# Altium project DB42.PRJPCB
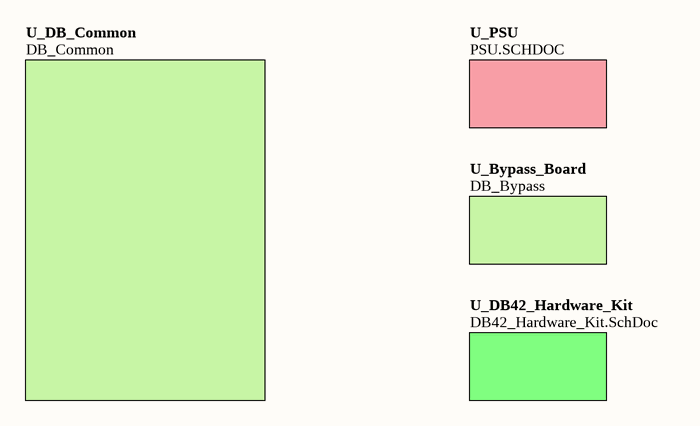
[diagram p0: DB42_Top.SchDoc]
ProjectAddress1: L3, 12A Rodborough Road; ProjectAddress2: Frenchs Forest; ProjectAddress3: NSW 2086; ProjectAddress4: Australia; ProjectAssyNum: D-820-0025; ProjectOrganization: Altium Limited; ProjectRevision: 01; ProjectTitle: DB42 - Daughter Board Spartan3; ProjectTotalSheets: 23
9 sheets, 129 parts. Net scope: hierarchical (ports join the sheet entries above them; power ports are global).
Board files: DB42.PcbDoc, DB42_Panel.PcbDoc
Sheets:
  DB42_Top.SchDoc
    U_PSU = PSU.SCHDOC
    U_DB42_Hardware_Kit = DB42_Hardware_Kit.SchDoc
  DEVICES.SchDoc
    U_FPGA = FPGA.SCHDOC
      U_FPGA_Power = FPGA_NonIO.SchDoc
      U_Bypass_3V3 = Bypass_FPGA_3V3.SchDoc
      U_Bypass_2V5 = Bypass_FPGA_2V5.SchDoc
      U_Bypass_1V2 = Bypass_FPGA_1V2.SchDoc

## Sheet DB42_Top.SchDoc: DB42 Top Level
size A4; Organization: Altium Limited.; Address1: Level 3, 12a Rodborough Rd; Address2: Frenchs Forest 2086; Address3: NSW; Address4: AUSTRALIA; DocumentNumber: 1; SheetNumber: 2; SheetTotal: 23

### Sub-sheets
U_Bypass_Board = DB_Bypass (file not in this document): no entries
U_DB42_Hardware_Kit = DB42_Hardware_Kit.SchDoc: no entries
U_DB_Common = DB_Common (file not in this document): no entries
U_PSU = PSU.SCHDOC: no entries

## Sheet PSU.SCHDOC: Power Supply Top Level
size A4; Organization: Altium Limited.; Address1: Level 3, 12a Rodborough Rd; Address2: Frenchs Forest 2086; Address3: NSW; Address4: AUSTRALIA; DocumentNumber: 10; SheetNumber: 10; SheetTotal: 23
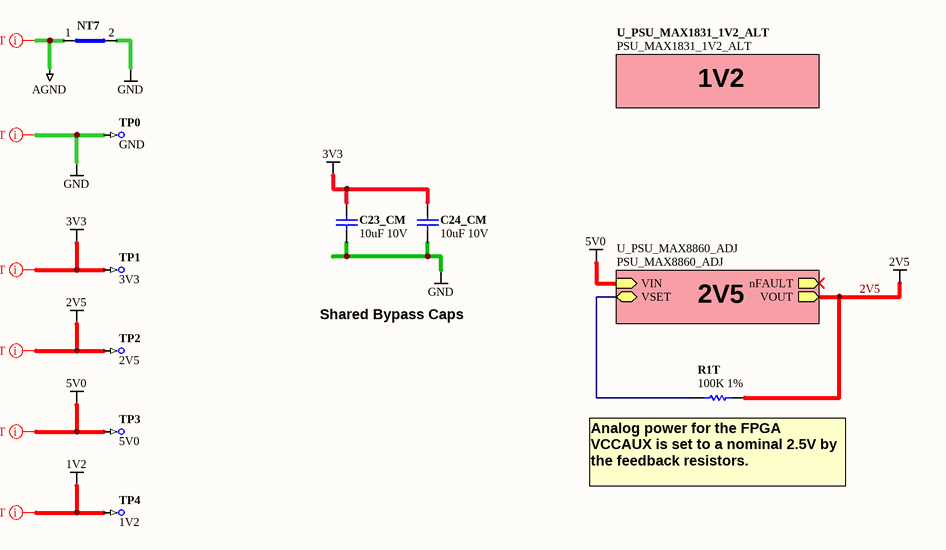
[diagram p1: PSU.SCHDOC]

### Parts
C23_CM  10uF 10V  [CAPC2012-STAR]
C24_CM  10uF 10V  [CAPC2012-STAR]
NT7  Net Tie SMT2  [NETTIE-SMT2-8X8]  (value not drawn)  (net tie, no BOM)
R1T  100K 1%  [RESC1005-STAR]
TP0  GND  [TestPin]  (no BOM)
TP1  3V3  [TestPin]  (no BOM)
TP2  2V5  [TestPin]  (no BOM)
TP3  5V0  [TestPin]  (no BOM)
TP4  1V2  [TestPin]  (no BOM)

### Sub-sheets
U_PSU_MAX1831_1V2_ALT = PSU_MAX1831_1V2_ALT (file not in this document): no entries
U_PSU_MAX8860_ADJ = PSU_MAX8860_ADJ (file not in this document): nFAULT (out), VIN (in), VOUT (out), VSET (bidir)

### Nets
1V2: TP4.1
2V5: R1T.2 TP2.1 ; sheet U_PSU_MAX8860_ADJ/VOUT
3V3: C23_CM.1 C24_CM.1 TP1.1
5V0: TP3.1 ; sheet U_PSU_MAX8860_ADJ/VIN
AGND: NT7.1(Net1)
GND: C23_CM.2 C24_CM.2 NT7.2(Net2) TP0.1
NetR1T_1: R1T.1 ; sheet U_PSU_MAX8860_ADJ/VSET

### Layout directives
net class PWRNET: 1V2, 2V5, 3V3, 5V0, AGND, GND

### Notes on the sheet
- 1V2
- Shared Bypass Caps
- 2V5
- (near R1T) Analog power for the FPGA VCCAUX is set to a nominal 2.5V by the feedback resistors.

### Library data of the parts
C23_CM C24_CM = D-101-0087: Capacitor, Ceramic, 10uF 10% 10V 0805 (2012) X5R; Polarity: Non-Polarized
NT7 = D-002-0002: Net-Tie, Surface Mount, 2 x 0.4mm x 0.2mm SMT Pads - For 0.2mm Track
R1T = D-100-0132: Resistor, 100K 1% 0402 (1005); Power Rating: 63 mW
TP0-TP4 = D-006-0000: Test Point, PCB Mount with Silkscreen Box

## Sheet DB42_Hardware_Kit.SchDoc: DB42 Hardware Kit
size A4; Organization: Altium Limited.; Address1: Level 3, 12a Rodborough Rd; Address2: Frenchs Forest 2086; Address3: NSW; Address4: AUSTRALIA; DocumentNumber: 9; SheetNumber: 9; SheetTotal: 23
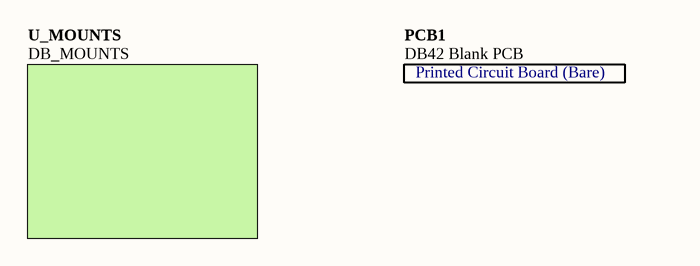
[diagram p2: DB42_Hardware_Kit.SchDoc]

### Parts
PCB1  DB42 Blank PCB  [DB42 Blank PCB]

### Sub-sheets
U_MOUNTS = DB_MOUNTS (file not in this document): no entries

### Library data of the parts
PCB1 = D-810-0025: DB42 Blank PCB - Daughter Board; ProjectPath: DB42.PrjPCB

## Sheet DEVICES.SchDoc: FPGA, LEDs and SRAM Memory
size A4; Organization: Altium Limited.; Address1: Level 3, 12a Rodborough Rd; Address2: Frenchs Forest 2086; Address3: NSW; Address4: AUSTRALIA; DocumentNumber: 2; SheetNumber: 3; SheetTotal: 23
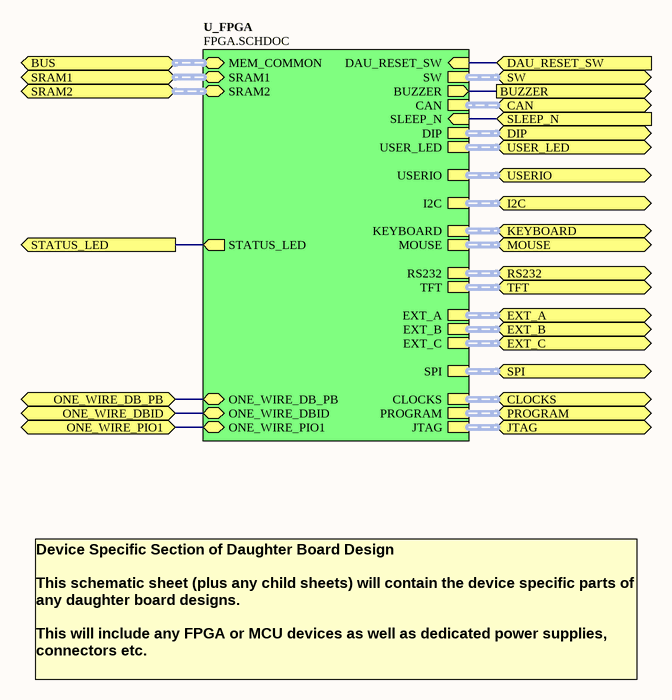
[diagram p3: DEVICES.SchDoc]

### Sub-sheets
U_FPGA = FPGA.SCHDOC: SRAM1 (harness SRAM-256Kx16), SRAM2 (harness SRAM-256Kx16), MEM_COMMON (harness HOSTMEMORY), DAU_RESET_SW (in), BUZZER (out), ONE_WIRE_DBID (bidir), ONE_WIRE_DB_PB (bidir), ONE_WIRE_PIO1 (bidir), JTAG (harness HardSoft_JTAG), SW (harness SW5), DIP (harness SW8), USERIO (harness IO36), EXT_A (harness PBIO), EXT_B (harness PBIO), EXT_C (harness PBIO), USER_LED (harness LED8), SPI (harness DAU_SPI), I2C (harness I2C), CAN (harness CAN_INT), RS232 (harness RS232_INT), KEYBOARD (harness PS2), MOUSE (harness PS2), TFT (harness DAU_TFT), PROGRAM (harness DAU_CTRL), CLOCKS (harness DAU_CLK), STATUS_LED (out), SLEEP_N (in)

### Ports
BUS (harness HOSTMEMORY), BUZZER (out), CAN, CLOCKS, DAU_RESET_SW (in), DIP, EXT_A, EXT_B, EXT_C, I2C, JTAG, KEYBOARD, MOUSE, ONE_WIRE_DB_PB (bidir), ONE_WIRE_DBID (bidir), ONE_WIRE_PIO1 (bidir), PROGRAM, RS232, SLEEP_N (in), SPI, SRAM1, SRAM2 (harness SRAM-256Kx16), STATUS_LED (out), SW, TFT, USER_LED, USERIO

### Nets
BUZZER: port BUZZER, sheet U_FPGA/BUZZER
DAU_RESET_SW: port DAU_RESET_SW, sheet U_FPGA/DAU_RESET_SW
ONE_WIRE_DB_PB: port ONE_WIRE_DB_PB, sheet U_FPGA/ONE_WIRE_DB_PB
ONE_WIRE_DBID: port ONE_WIRE_DBID, sheet U_FPGA/ONE_WIRE_DBID
ONE_WIRE_PIO1: port ONE_WIRE_PIO1, sheet U_FPGA/ONE_WIRE_PIO1
SLEEP_N: port SLEEP_N, sheet U_FPGA/SLEEP_N
STATUS_LED: port STATUS_LED, sheet U_FPGA/STATUS_LED

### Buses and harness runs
harness port BUS = sheet U_FPGA/MEM_COMMON
harness port CAN = sheet U_FPGA/CAN
harness port CLOCKS = sheet U_FPGA/CLOCKS
harness port DIP = sheet U_FPGA/DIP
harness port EXT_A = sheet U_FPGA/EXT_A
harness port EXT_B = sheet U_FPGA/EXT_B
harness port EXT_C = sheet U_FPGA/EXT_C
harness port I2C = sheet U_FPGA/I2C
harness port JTAG = sheet U_FPGA/JTAG
harness port KEYBOARD = sheet U_FPGA/KEYBOARD
harness port MOUSE = sheet U_FPGA/MOUSE
harness port PROGRAM = sheet U_FPGA/PROGRAM
harness port RS232 = sheet U_FPGA/RS232
harness port SPI = sheet U_FPGA/SPI
harness port SRAM1 = sheet U_FPGA/SRAM1
harness port SRAM2 = sheet U_FPGA/SRAM2
harness port SW = sheet U_FPGA/SW
harness port TFT = sheet U_FPGA/TFT
harness port USER_LED = sheet U_FPGA/USER_LED
harness port USERIO = sheet U_FPGA/USERIO

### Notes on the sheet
- Device Specific Section of Daughter Board Design
  This schematic sheet (plus any child sheets) will contain the device specific parts of any daughter board designs.
  This will include any FPGA or MCU devices as well as dedicated power supplies, connectors etc.

## Sheet FPGA.SCHDOC: FPGA Connections
size A2; Organization: Altium Limited.; Address1: Level 3, 12a Rodborough Rd; Address2: Frenchs Forest 2086; Address3: NSW; Address4: AUSTRALIA; DocumentNumber: 3; SheetNumber: 4; SheetTotal: 23; PageSetup: Record=PageOptions|CenterHorizontal=True|CenterVertical=True|PrintScale=0.71|XCorrection=1.00|YCorrection=1.00|PrintKind=0|BorderSize=5000000|LeftOffset=0|BottomOffset=0|Orientation=2|PaperLength=4199|PaperWidth=2969|Scale=100|PaperSource=7|PrintQuality=600|MediaType=1|DitherType=10|PaperKind=A3 (297 x 420 mm)|PrintScaleMode=1
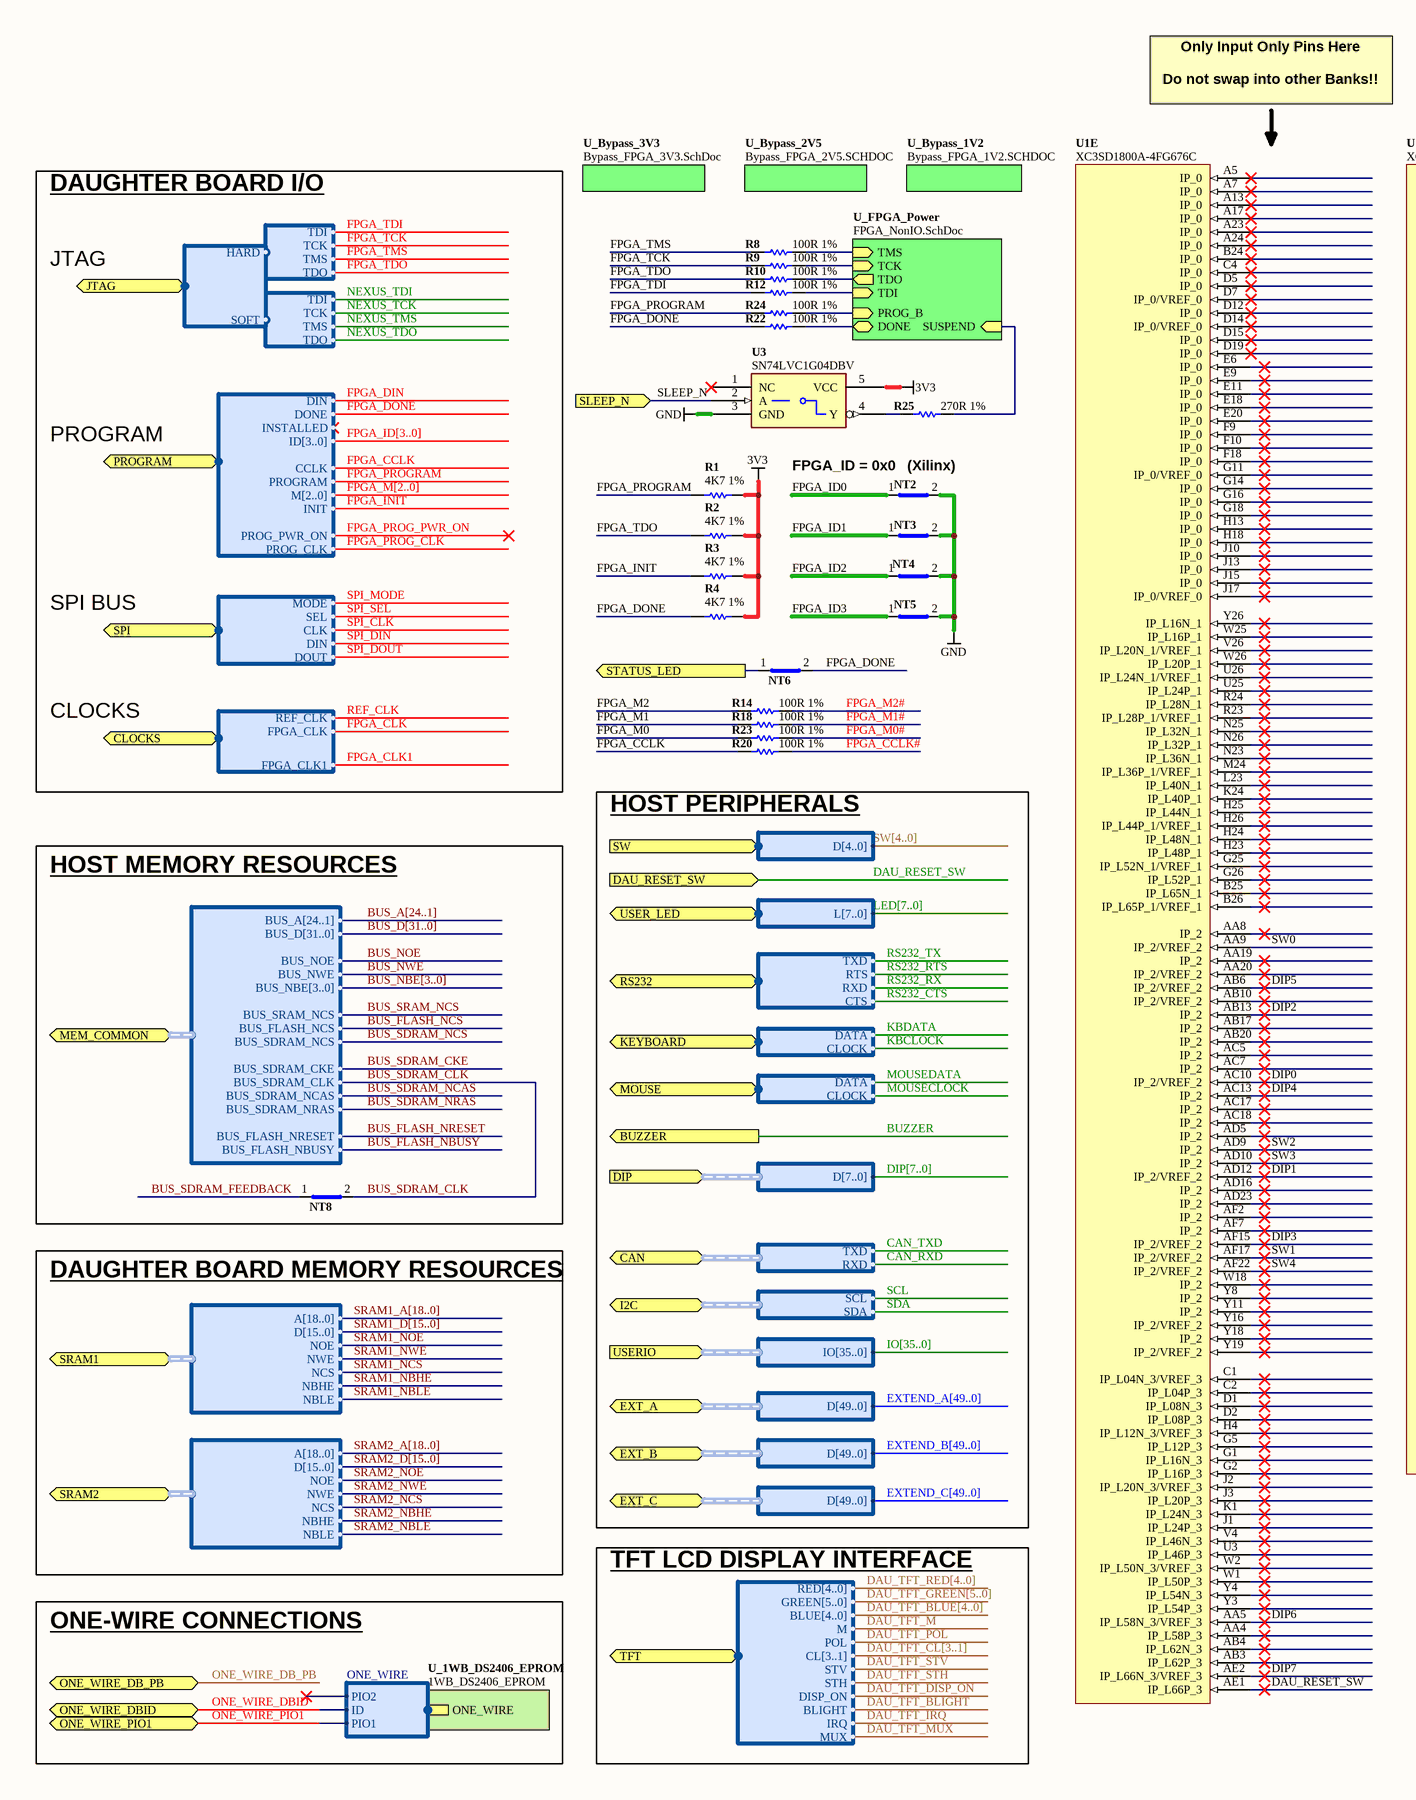
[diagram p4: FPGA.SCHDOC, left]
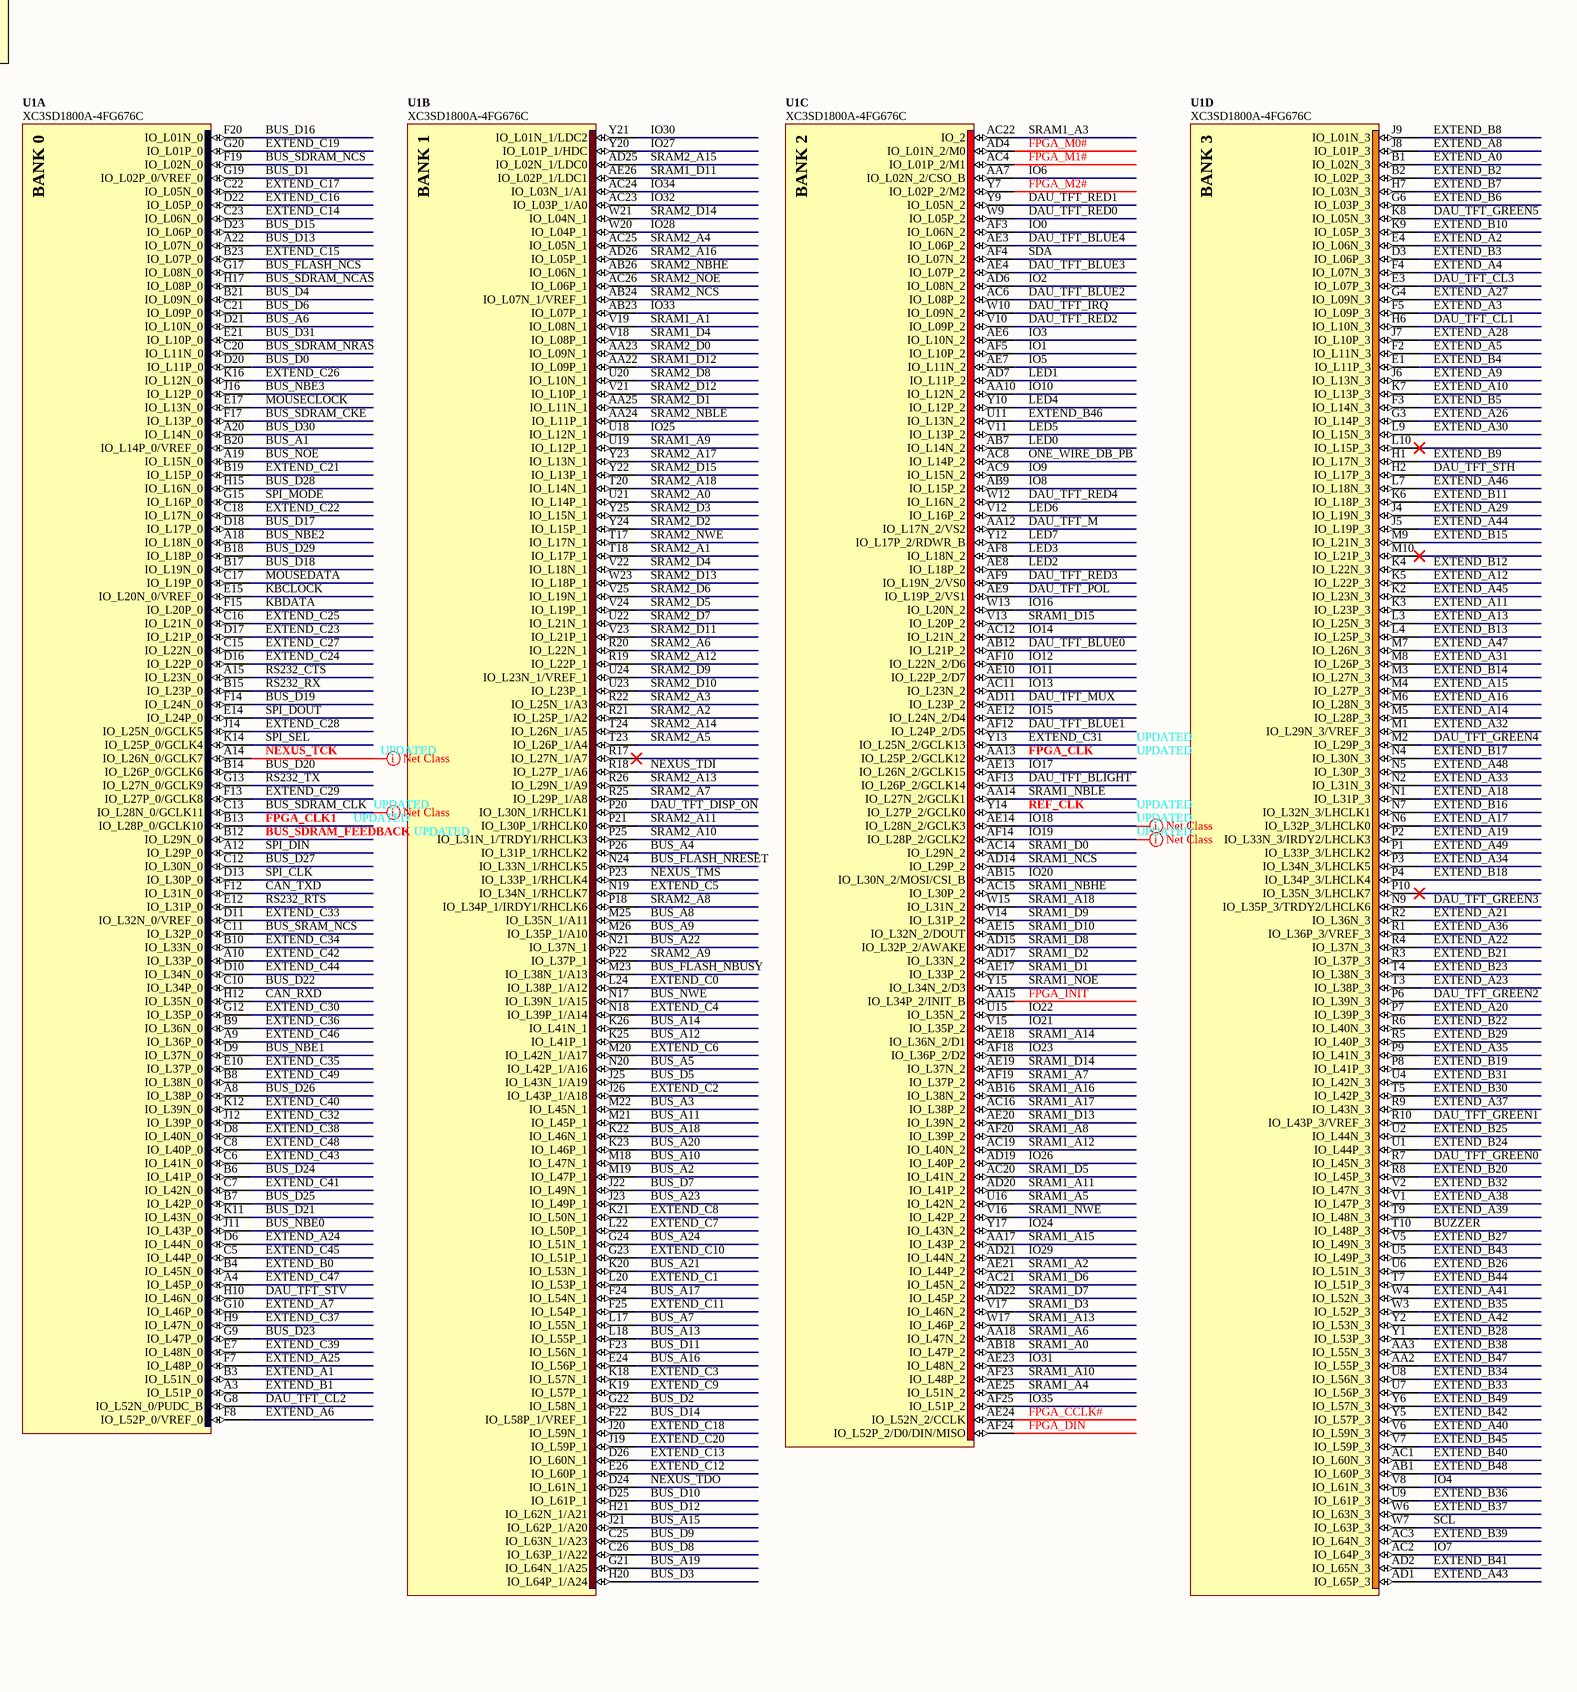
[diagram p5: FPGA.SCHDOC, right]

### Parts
NT2  Net Tie SMT2  [NETTIE-SMT2-8X8]  (value not drawn)  (net tie, no BOM)
NT3  Net Tie SMT2  [NETTIE-SMT2-8X8]  (value not drawn)  (net tie, no BOM)
NT4  Net Tie SMT2  [NETTIE-SMT2-8X8]  (value not drawn)  (net tie, no BOM)
NT5  Net Tie SMT2  [NETTIE-SMT2-8X8]  (value not drawn)  (net tie, no BOM)
NT6  Net Tie SMT2  [NETTIE-SMT2-8X8]  (value not drawn)  (net tie, no BOM)
NT8  Net Tie SMT2  [NETTIE-SMT2-8X8]  (value not drawn)  (net tie, no BOM)
R1  4K7 1%  [RESC1005-STAR]
R2  4K7 1%  [RESC1005-STAR]
R3  4K7 1%  [RESC1005-STAR]
R4  4K7 1%  [RESC1005-STAR]
R8  100R 1%  [RESC1005-STAR]
R9  100R 1%  [RESC1005-STAR]
R10  100R 1%  [RESC1005-STAR]
R12  100R 1%  [RESC1005-STAR]
R14  100R 1%  [RESC1005-STAR]
R18  100R 1%  [RESC1005-STAR]
R20  100R 1%  [RESC1005-STAR]
R22  100R 1%  [RESC1005-STAR]
R23  100R 1%  [RESC1005-STAR]
R24  100R 1%  [RESC1005-STAR]
R25  270R 1%  [RESC1005-STAR]
U1  XC3SD1800A-4FG676C  [BGA100P26X26-676]  (parts A,B,C,D,E of 8)
U3  SN74LVC1G04DBV  [SOT95P280-5]

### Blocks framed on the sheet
HOST MEMORY RESOURCES: NT8

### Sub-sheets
U_1WB_DS2406_EPROM = 1WB_DS2406_EPROM (file not in this document): ONE_WIRE (harness ONE_WIRE)
U_Bypass_1V2 = Bypass_FPGA_1V2.SCHDOC: no entries
U_Bypass_2V5 = Bypass_FPGA_2V5.SCHDOC: no entries
U_Bypass_3V3 = Bypass_FPGA_3V3.SchDoc: no entries
U_FPGA_Power = FPGA_NonIO.SchDoc: TMS (in), DONE (bidir), TCK (in), TDI (in), PROG_B (in), TDO (out), SUSPEND (in)

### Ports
BUZZER (out), CAN (harness CAN_INT), CLOCKS (harness DAU_CLK), DAU_RESET_SW (in), DIP (harness SW8), EXT_A (harness PBIO), EXT_B (harness PBIO), EXT_C (harness PBIO), I2C (harness I2C), JTAG (harness HARDSOFT_JTAG), KEYBOARD (harness PS2), MEM_COMMON (harness HOSTMEMORY), MOUSE (harness PS2), ONE_WIRE_DB_PB (bidir), ONE_WIRE_DBID (bidir), ONE_WIRE_PIO1 (bidir), PROGRAM (harness DAU_CTRL), RS232 (harness RS232_INT), SLEEP_N (in), SPI (harness DAU_SPI), SRAM1 (harness SRAM-256Kx16), SRAM2 (harness SRAM-256Kx16), STATUS_LED (out), SW (harness SW5), TFT (harness DAU_TFT), USER_LED (harness LED8), USERIO (harness IO36)

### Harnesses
ONE_WIRE: ID, PIO1, PIO2
SRAM-256Kx16: A[18..0], D[15..0], NCS, NWE, NOE, NBHE, NBLE
HOSTMEMORY: BUS_A[24..1], BUS_D[31..0], BUS_NOE, BUS_NWE, BUS_NBE[3..0], BUS_SRAM_NCS, BUS_FLASH_NCS, BUS_SDRAM_NCS, BUS_SDRAM_CKE, BUS_SDRAM_CLK, BUS_SDRAM_NCAS, BUS_SDRAM_NRAS, BUS_FLASH_NRESET, BUS_FLASH_NBUSY
DAU_CLK: REF_CLK, FPGA_CLK, FPGA_CLK1
DAU_SPI: MODE, SEL, CLK, DIN, DOUT
DAU_CTRL: DIN, DONE, INSTALLED, ID[3..0], CCLK, PROGRAM, M[2..0], INIT, PROG_PWR_ON, PROG_CLK
JTAG: TMS, TDO, TDI, TCK
HARDSOFT_JTAG: HARD, SOFT
LED8: L[7..0]
SW5: D[4..0]
DAU_TFT: RED[4..0], GREEN[5..0], BLUE[4..0], M, POL, CL[3..1], STV, STH, DISP_ON, BLIGHT, IRQ, MUX
PS2: DATA, CLOCK
RS232_INT: RXD, TXD, RTS, CTS
IO36: IO[35..0]
SW8: D[7..0]
CAN_INT: TXD, RXD
I2C: SCL, SDA
PBIO: D[49..0]

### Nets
3V3: R1.2 R2.2 R3.2 R4.2 U3.5(VCC)
GND: NT2.2(Net2) NT3.2(Net2) NT4.2(Net2) NT5.2(Net2) U3.3(GND)
BUS_A1: U1.B20(IO_L14P_0/VREF_0)
BUS_A2: U1.M19(IO_L47P_1)
BUS_A3: U1.M22(IO_L45N_1)
BUS_A4: U1.P26(IO_L31P_1/RHCLK2)
BUS_A5: U1.N20(IO_L42P_1/A16)
BUS_A6: U1.D21(IO_L10N_0)
BUS_A7: U1.L17(IO_L55N_1)
BUS_A8: U1.M25(IO_L35N_1/A11)
BUS_A9: U1.M26(IO_L35P_1/A10)
BUS_A10: U1.M18(IO_L47N_1)
BUS_A11: U1.M21(IO_L45P_1)
BUS_A12: U1.K25(IO_L41P_1)
BUS_A13: U1.L18(IO_L55P_1)
BUS_A14: U1.K26(IO_L41N_1)
BUS_A15: U1.J21(IO_L62P_1/A20)
BUS_A16: U1.E24(IO_L56P_1)
BUS_A17: U1.F24(IO_L54N_1)
BUS_A18: U1.K22(IO_L46N_1)
BUS_A19: U1.G21(IO_L64N_1/A25)
BUS_A20: U1.K23(IO_L46P_1)
BUS_A21: U1.K20(IO_L53N_1)
BUS_A22: U1.N21(IO_L37N_1)
BUS_A23: U1.J23(IO_L49P_1)
BUS_A24: U1.G24(IO_L51N_1)
BUS_D0: U1.D20(IO_L11P_0)
BUS_D1: U1.G19(IO_L02P_0/VREF_0)
BUS_D2: U1.G22(IO_L58N_1)
BUS_D3: U1.H20(IO_L64P_1/A24)
BUS_D4: U1.B21(IO_L09N_0)
BUS_D5: U1.J25(IO_L43N_1/A19)
BUS_D6: U1.C21(IO_L09P_0)
BUS_D7: U1.J22(IO_L49N_1)
BUS_D8: U1.C26(IO_L63P_1/A22)
BUS_D9: U1.C25(IO_L63N_1/A23)
BUS_D10: U1.D25(IO_L61P_1)
BUS_D11: U1.F23(IO_L56N_1)
BUS_D12: U1.H21(IO_L62N_1/A21)
BUS_D13: U1.A22(IO_L07N_0)
BUS_D14: U1.F22(IO_L58P_1/VREF_1)
BUS_D15: U1.D23(IO_L06P_0)
BUS_D16: U1.F20(IO_L01N_0)
BUS_D17: U1.D18(IO_L17P_0)
BUS_D18: U1.B17(IO_L19N_0)
BUS_D19: U1.F14(IO_L24N_0)
BUS_D20: U1.B14(IO_L26P_0/GCLK6)
BUS_D21: U1.K11(IO_L43N_0)
BUS_D22: U1.C10(IO_L34P_0)
BUS_D23: U1.G9(IO_L47P_0)
BUS_D24: U1.B6(IO_L41P_0)
BUS_D25: U1.B7(IO_L42P_0)
BUS_D26: U1.A8(IO_L38P_0)
BUS_D27: U1.C12(IO_L30N_0)
BUS_D28: U1.H15(IO_L16N_0)
BUS_D29: U1.B18(IO_L18P_0)
BUS_D30: U1.A20(IO_L14N_0)
BUS_D31: U1.E21(IO_L10P_0)
BUS_FLASH_NBUSY: U1.M23(IO_L38N_1/A13) ; port MEM_COMMON.BUS_FLASH_NBUSY
BUS_FLASH_NCS: U1.G17(IO_L08N_0) ; port MEM_COMMON.BUS_FLASH_NCS
BUS_FLASH_NRESET: U1.N24(IO_L33N_1/RHCLK5) ; port MEM_COMMON.BUS_FLASH_NRESET
BUS_NBE0: U1.J11(IO_L43P_0)
BUS_NBE1: U1.D9(IO_L37N_0)
BUS_NBE2: U1.A18(IO_L18N_0)
BUS_NBE3: U1.J16(IO_L12P_0)
BUS_NOE: U1.A19(IO_L15N_0) ; port MEM_COMMON.BUS_NOE
BUS_NWE: U1.N17(IO_L39N_1/A15) ; port MEM_COMMON.BUS_NWE
BUS_SDRAM_CKE: U1.F17(IO_L13P_0) ; port MEM_COMMON.BUS_SDRAM_CKE
BUS_SDRAM_CLK: NT8.2(Net2) U1.C13(IO_L28N_0/GCLK11) ; port MEM_COMMON.BUS_SDRAM_CLK
BUS_SDRAM_FEEDBACK: NT8.1(Net1) U1.B12(IO_L29N_0)
BUS_SDRAM_NCAS: U1.H17(IO_L08P_0) ; port MEM_COMMON.BUS_SDRAM_NCAS
BUS_SDRAM_NCS: U1.F19(IO_L02N_0) ; port MEM_COMMON.BUS_SDRAM_NCS
BUS_SDRAM_NRAS: U1.C20(IO_L11N_0) ; port MEM_COMMON.BUS_SDRAM_NRAS
BUS_SRAM_NCS: U1.C11(IO_L32P_0) ; port MEM_COMMON.BUS_SRAM_NCS
BUZZER: U1.T10(IO_L48P_3) ; port BUZZER
CAN_RXD: U1.H12(IO_L35N_0) ; port CAN.RXD
CAN_TXD: U1.F12(IO_L31N_0) ; port CAN.TXD
DAU_RESET_SW: U1.AE1(IP_L66P_3) ; port DAU_RESET_SW
DAU_TFT_BLIGHT: U1.AF13(IO_L26P_2/GCLK14) ; port TFT.BLIGHT
DAU_TFT_BLUE0: U1.AB12(IO_L21P_2)
DAU_TFT_BLUE1: U1.AF12(IO_L24P_2/D5)
DAU_TFT_BLUE2: U1.AC6(IO_L08P_2)
DAU_TFT_BLUE3: U1.AE4(IO_L07P_2)
DAU_TFT_BLUE4: U1.AE3(IO_L06P_2)
DAU_TFT_CL1: U1.H6(IO_L10N_3)
DAU_TFT_CL2: U1.G8(IO_L52N_0/PUDC_B)
DAU_TFT_CL3: U1.E3(IO_L07P_3)
DAU_TFT_DISP_ON: U1.P20(IO_L30N_1/RHCLK1) ; port TFT.DISP_ON
DAU_TFT_GREEN0: U1.R7(IO_L45N_3)
DAU_TFT_GREEN1: U1.R10(IO_L43P_3/VREF_3)
DAU_TFT_GREEN2: U1.P6(IO_L39N_3)
DAU_TFT_GREEN3: U1.N9(IO_L35P_3/TRDY2/LHCLK6)
DAU_TFT_GREEN4: U1.M2(IO_L29P_3)
DAU_TFT_GREEN5: U1.K8(IO_L05N_3)
DAU_TFT_IRQ: U1.W10(IO_L09N_2) ; port TFT.IRQ
DAU_TFT_M: U1.AA12(IO_L17N_2/VS2) ; port TFT.M
DAU_TFT_MUX: U1.AD11(IO_L23P_2) ; port TFT.MUX
DAU_TFT_POL: U1.AE9(IO_L19P_2/VS1) ; port TFT.POL
DAU_TFT_RED0: U1.W9(IO_L05P_2)
DAU_TFT_RED1: U1.Y9(IO_L05N_2)
DAU_TFT_RED2: U1.V10(IO_L09P_2)
DAU_TFT_RED3: U1.AF9(IO_L19N_2/VS0)
DAU_TFT_RED4: U1.W12(IO_L16N_2)
DAU_TFT_STH: U1.H2(IO_L17P_3) ; port TFT.STH
DAU_TFT_STV: U1.H10(IO_L46N_0) ; port TFT.STV
DIP0: U1.AC10(IP_2/VREF_2)
DIP1: U1.AD12(IP_2/VREF_2)
DIP2: U1.AB13(IP_2)
DIP3: U1.AF15(IP_2/VREF_2)
DIP4: U1.AC13(IP_2)
DIP5: U1.AB6(IP_2/VREF_2)
DIP6: U1.AA5(IP_L58N_3/VREF_3)
DIP7: U1.AE2(IP_L66N_3/VREF_3)
DONE: R22.2 ; sheet U_FPGA_Power/DONE
EXTEND_A0: U1.B1(IO_L02N_3)
EXTEND_A1: U1.B3(IO_L51N_0)
EXTEND_A2: U1.E4(IO_L06N_3)
EXTEND_A3: U1.F5(IO_L09P_3)
EXTEND_A4: U1.F4(IO_L07N_3)
EXTEND_A5: U1.F2(IO_L11N_3)
EXTEND_A6: U1.F8(IO_L52P_0/VREF_0)
EXTEND_A7: U1.G10(IO_L46P_0)
EXTEND_A8: U1.J8(IO_L01P_3)
EXTEND_A9: U1.J6(IO_L13N_3)
EXTEND_A10: U1.K7(IO_L13P_3)
EXTEND_A11: U1.K3(IO_L23P_3)
EXTEND_A12: U1.K5(IO_L22P_3)
EXTEND_A13: U1.L3(IO_L25N_3)
EXTEND_A14: U1.M5(IO_L28P_3)
EXTEND_A15: U1.M4(IO_L27P_3)
EXTEND_A16: U1.M6(IO_L28N_3)
EXTEND_A17: U1.N6(IO_L32P_3/LHCLK0)
EXTEND_A18: U1.N1(IO_L31P_3)
EXTEND_A19: U1.P2(IO_L33N_3/IRDY2/LHCLK3)
EXTEND_A20: U1.P7(IO_L39P_3)
EXTEND_A21: U1.R2(IO_L36N_3)
EXTEND_A22: U1.R4(IO_L37N_3)
EXTEND_A23: U1.T3(IO_L38P_3)
EXTEND_A24: U1.D6(IO_L44N_0)
EXTEND_A25: U1.F7(IO_L48P_0)
EXTEND_A26: U1.G3(IO_L14P_3)
EXTEND_A27: U1.G4(IO_L09N_3)
EXTEND_A28: U1.J7(IO_L10P_3)
EXTEND_A29: U1.J4(IO_L19N_3)
EXTEND_A30: U1.L9(IO_L15N_3)
EXTEND_A31: U1.M8(IO_L26P_3)
EXTEND_A32: U1.M1(IO_L29N_3/VREF_3)
EXTEND_A33: U1.N2(IO_L31N_3)
EXTEND_A34: U1.P3(IO_L34N_3/LHCLK5)
EXTEND_A35: U1.P9(IO_L41N_3)
EXTEND_A36: U1.R1(IO_L36P_3/VREF_3)
EXTEND_A37: U1.R9(IO_L43N_3)
EXTEND_A38: U1.V1(IO_L47P_3)
EXTEND_A39: U1.T9(IO_L48N_3)
EXTEND_A40: U1.V6(IO_L59N_3)
EXTEND_A41: U1.W4(IO_L52N_3)
EXTEND_A42: U1.Y2(IO_L53N_3)
EXTEND_A43: U1.AD1(IO_L65P_3)
EXTEND_A44: U1.J5(IO_L19P_3)
EXTEND_A45: U1.K2(IO_L23N_3)
EXTEND_A46: U1.L7(IO_L18N_3)
EXTEND_A47: U1.M7(IO_L26N_3)
EXTEND_A48: U1.N5(IO_L30P_3)
EXTEND_A49: U1.P1(IO_L33P_3/LHCLK2)
EXTEND_B0: U1.B4(IO_L45N_0)
EXTEND_B1: U1.A3(IO_L51P_0)
EXTEND_B2: U1.B2(IO_L02P_3)
EXTEND_B3: U1.D3(IO_L06P_3)
EXTEND_B4: U1.E1(IO_L11P_3)
EXTEND_B5: U1.F3(IO_L14N_3)
EXTEND_B6: U1.G6(IO_L03P_3)
EXTEND_B7: U1.H7(IO_L03N_3)
EXTEND_B8: U1.J9(IO_L01N_3)
EXTEND_B9: U1.H1(IO_L17N_3)
EXTEND_B10: U1.K9(IO_L05P_3)
EXTEND_B11: U1.K6(IO_L18P_3)
EXTEND_B12: U1.K4(IO_L22N_3)
EXTEND_B13: U1.L4(IO_L25P_3)
EXTEND_B14: U1.M3(IO_L27N_3)
EXTEND_B15: U1.M9(IO_L21N_3)
EXTEND_B16: U1.N7(IO_L32N_3/LHCLK1)
EXTEND_B17: U1.N4(IO_L30N_3)
EXTEND_B18: U1.P4(IO_L34P_3/LHCLK4)
EXTEND_B19: U1.P8(IO_L41P_3)
EXTEND_B20: U1.R8(IO_L45P_3)
EXTEND_B21: U1.R3(IO_L37P_3)
EXTEND_B22: U1.R6(IO_L40N_3)
EXTEND_B23: U1.T4(IO_L38N_3)
EXTEND_B24: U1.U1(IO_L44P_3)
EXTEND_B25: U1.U2(IO_L44N_3)
EXTEND_B26: U1.U6(IO_L51N_3)
EXTEND_B27: U1.V5(IO_L49N_3)
EXTEND_B28: U1.Y1(IO_L53P_3)
EXTEND_B29: U1.R5(IO_L40P_3)
EXTEND_B30: U1.T5(IO_L42P_3)
EXTEND_B31: U1.U4(IO_L42N_3)
EXTEND_B32: U1.V2(IO_L47N_3)
EXTEND_B33: U1.U7(IO_L56P_3)
EXTEND_B34: U1.U8(IO_L56N_3)
EXTEND_B35: U1.W3(IO_L52P_3)
EXTEND_B36: U1.U9(IO_L61P_3)
EXTEND_B37: U1.W6(IO_L63N_3)
EXTEND_B38: U1.AA3(IO_L55N_3)
EXTEND_B39: U1.AC3(IO_L64N_3)
EXTEND_B40: U1.AC1(IO_L60N_3)
EXTEND_B41: U1.AD2(IO_L65N_3)
EXTEND_B42: U1.Y5(IO_L57P_3)
EXTEND_B43: U1.U5(IO_L49P_3)
EXTEND_B44: U1.T7(IO_L51P_3)
EXTEND_B45: U1.V7(IO_L59P_3)
EXTEND_B46: U1.U11(IO_L13N_2)
EXTEND_B47: U1.AA2(IO_L55P_3)
EXTEND_B48: U1.AB1(IO_L60P_3)
EXTEND_B49: U1.Y6(IO_L57N_3)
EXTEND_C0: U1.L24(IO_L38P_1/A12)
EXTEND_C1: U1.L20(IO_L53P_1)
EXTEND_C2: U1.J26(IO_L43P_1/A18)
EXTEND_C3: U1.K18(IO_L57N_1)
EXTEND_C4: U1.N18(IO_L39P_1/A14)
EXTEND_C5: U1.N19(IO_L34N_1/RHCLK7)
EXTEND_C6: U1.M20(IO_L42N_1/A17)
EXTEND_C7: U1.L22(IO_L50P_1)
EXTEND_C8: U1.K21(IO_L50N_1)
EXTEND_C9: U1.K19(IO_L57P_1)
EXTEND_C10: U1.G23(IO_L51P_1)
EXTEND_C11: U1.F25(IO_L54P_1)
EXTEND_C12: U1.E26(IO_L60P_1)
EXTEND_C13: U1.D26(IO_L60N_1)
EXTEND_C14: U1.C23(IO_L06N_0)
EXTEND_C15: U1.B23(IO_L07P_0)
EXTEND_C16: U1.D22(IO_L05P_0)
EXTEND_C17: U1.C22(IO_L05N_0)
EXTEND_C18: U1.J20(IO_L59N_1)
EXTEND_C19: U1.G20(IO_L01P_0)
EXTEND_C20: U1.J19(IO_L59P_1)
EXTEND_C21: U1.B19(IO_L15P_0)
EXTEND_C22: U1.C18(IO_L17N_0)
EXTEND_C23: U1.D17(IO_L21P_0)
EXTEND_C24: U1.D16(IO_L22P_0)
EXTEND_C25: U1.C16(IO_L21N_0)
EXTEND_C26: U1.K16(IO_L12N_0)
EXTEND_C27: U1.C15(IO_L22N_0)
EXTEND_C28: U1.J14(IO_L25N_0/GCLK5)
EXTEND_C29: U1.F13(IO_L27P_0/GCLK8)
EXTEND_C30: U1.G12(IO_L35P_0)
EXTEND_C31: U1.Y13(IO_L25N_2/GCLK13)
EXTEND_C32: U1.J12(IO_L39P_0)
EXTEND_C33: U1.D11(IO_L32N_0/VREF_0)
EXTEND_C34: U1.B10(IO_L33N_0)
EXTEND_C35: U1.E10(IO_L37P_0)
EXTEND_C36: U1.B9(IO_L36N_0)
EXTEND_C37: U1.H9(IO_L47N_0)
EXTEND_C38: U1.D8(IO_L40N_0)
EXTEND_C39: U1.E7(IO_L48N_0)
EXTEND_C40: U1.K12(IO_L39N_0)
EXTEND_C41: U1.C7(IO_L42N_0)
EXTEND_C42: U1.A10(IO_L33P_0)
EXTEND_C43: U1.C6(IO_L41N_0)
EXTEND_C44: U1.D10(IO_L34N_0)
EXTEND_C45: U1.C5(IO_L44P_0)
EXTEND_C46: U1.A9(IO_L36P_0)
EXTEND_C47: U1.A4(IO_L45P_0)
EXTEND_C48: U1.C8(IO_L40P_0)
EXTEND_C49: U1.B8(IO_L38N_0)
FPGA_CCLK: R20.1 ; port PROGRAM.CCLK
FPGA_CCLK#: R20.2 U1.AE24(IO_L52N_2/CCLK)
FPGA_CLK: U1.AA13(IO_L25P_2/GCLK12) ; port CLOCKS.FPGA_CLK
FPGA_CLK1: U1.B13(IO_L28P_0/GCLK10) ; port CLOCKS.FPGA_CLK1
FPGA_DIN: U1.AF24(IO_L52P_2/D0/DIN/MISO) ; port PROGRAM.DIN
FPGA_DONE: NT6.2(Net2) R4.1 R22.1 ; port PROGRAM.DONE
FPGA_ID0: NT2.1(Net1)
FPGA_ID1: NT3.1(Net1)
FPGA_ID2: NT4.1(Net1)
FPGA_ID3: NT5.1(Net1)
FPGA_INIT: R3.1 U1.AA15(IO_L34P_2/INIT_B) ; port PROGRAM.INIT
FPGA_M0: R23.1
FPGA_M0#: R23.2 U1.AD4(IO_L01N_2/M0)
FPGA_M1: R18.1
FPGA_M1#: R18.2 U1.AC4(IO_L01P_2/M1)
FPGA_M2: R14.1
FPGA_M2#: R14.2 U1.Y7(IO_L02P_2/M2)
FPGA_PROGRAM: R1.1 R24.1 ; port PROGRAM.PROGRAM
FPGA_TCK: R9.1 ; harness JTAG.TCK
FPGA_TDI: R12.1 ; harness JTAG.TDI
FPGA_TDO: R2.1 R10.1 ; harness JTAG.TDO
FPGA_TMS: R8.1 ; harness JTAG.TMS
IO0: U1.AF3(IO_L06N_2)
IO1: U1.AF5(IO_L10P_2)
IO2: U1.AD6(IO_L08N_2)
IO3: U1.AE6(IO_L10N_2)
IO4: U1.V8(IO_L61N_3)
IO5: U1.AE7(IO_L11N_2)
IO6: U1.AA7(IO_L02N_2/CSO_B)
IO7: U1.AC2(IO_L64P_3)
IO8: U1.AB9(IO_L15P_2)
IO9: U1.AC9(IO_L15N_2)
IO10: U1.AA10(IO_L12N_2)
IO11: U1.AE10(IO_L22P_2/D7)
IO12: U1.AF10(IO_L22N_2/D6)
IO13: U1.AC11(IO_L23N_2)
IO14: U1.AC12(IO_L21N_2)
IO15: U1.AE12(IO_L24N_2/D4)
IO16: U1.W13(IO_L20N_2)
IO17: U1.AE13(IO_L26N_2/GCLK15)
IO18: U1.AE14(IO_L28N_2/GCLK3)
IO19: U1.AF14(IO_L28P_2/GCLK2)
IO20: U1.AB15(IO_L30N_2/MOSI/CSI_B)
IO21: U1.V15(IO_L35P_2)
IO22: U1.U15(IO_L35N_2)
IO23: U1.AF18(IO_L36P_2/D2)
IO24: U1.Y17(IO_L43N_2)
IO25: U1.U18(IO_L12N_1)
IO26: U1.AD19(IO_L40P_2)
IO27: U1.Y20(IO_L01P_1/HDC)
IO28: U1.W20(IO_L04P_1)
IO29: U1.AD21(IO_L44N_2)
IO30: U1.Y21(IO_L01N_1/LDC2)
IO31: U1.AE23(IO_L48N_2)
IO32: U1.AC23(IO_L03P_1/A0)
IO33: U1.AB23(IO_L07P_1)
IO34: U1.AC24(IO_L03N_1/A1)
IO35: U1.AF25(IO_L51P_2)
KBCLOCK: U1.E15(IO_L20N_0/VREF_0) ; port KEYBOARD.CLOCK
KBDATA: U1.F15(IO_L20P_0) ; port KEYBOARD.DATA
LED0: U1.AB7(IO_L14N_2)
LED1: U1.AD7(IO_L11P_2)
LED2: U1.AE8(IO_L18P_2)
LED3: U1.AF8(IO_L18N_2)
LED4: U1.Y10(IO_L12P_2)
LED5: U1.V11(IO_L13P_2)
LED6: U1.V12(IO_L16P_2)
LED7: U1.Y12(IO_L17P_2/RDWR_B)
MOUSECLOCK: U1.E17(IO_L13N_0) ; port MOUSE.CLOCK
MOUSEDATA: U1.C17(IO_L19P_0) ; port MOUSE.DATA
NEXUS_TCK: U1.A14(IO_L26N_0/GCLK7) ; harness JTAG.TCK
NEXUS_TDI: U1.R18(IO_L27P_1/A6) ; harness JTAG.TDI
NEXUS_TDO: U1.D24(IO_L61N_1) ; harness JTAG.TDO
NEXUS_TMS: U1.P23(IO_L33P_1/RHCLK4) ; harness JTAG.TMS
ONE_WIRE_DB_PB: U1.AC8(IO_L14P_2) ; port ONE_WIRE_DB_PB
ONE_WIRE_DBID: port ONE_WIRE_DBID, sheet U_1WB_DS2406_EPROM/ONE_WIRE.ID
ONE_WIRE_PIO1: port ONE_WIRE_PIO1, sheet U_1WB_DS2406_EPROM/ONE_WIRE.PIO1
PROG_B: R24.2 ; sheet U_FPGA_Power/PROG_B
REF_CLK: U1.Y14(IO_L27P_2/GCLK0) ; port CLOCKS.REF_CLK
RS232_CTS: U1.A15(IO_L23N_0) ; port RS232.CTS
RS232_RTS: U1.E12(IO_L31P_0) ; port RS232.RTS
RS232_RX: U1.B15(IO_L23P_0) ; port RS232.RXD
RS232_TX: U1.G13(IO_L27N_0/GCLK9) ; port RS232.TXD
SCL: U1.W7(IO_L63P_3) ; port I2C.SCL
SDA: U1.AF4(IO_L07N_2) ; port I2C.SDA
SLEEP_N: U3.2(A) ; port SLEEP_N
SPI_CLK: U1.D13(IO_L30P_0) ; port SPI.CLK
SPI_DIN: U1.A12(IO_L29P_0) ; port SPI.DIN
SPI_DOUT: U1.E14(IO_L24P_0) ; port SPI.DOUT
SPI_MODE: U1.G15(IO_L16P_0) ; port SPI.MODE
SPI_SEL: U1.K14(IO_L25P_0/GCLK4) ; port SPI.SEL
SRAM1_A0: U1.AB18(IO_L47P_2)
SRAM1_A1: U1.V19(IO_L08N_1)
SRAM1_A2: U1.AE21(IO_L44P_2)
SRAM1_A3: U1.AC22(IO_2)
SRAM1_A4: U1.AE25(IO_L51N_2)
SRAM1_A5: U1.U16(IO_L42N_2)
SRAM1_A6: U1.AA18(IO_L47N_2)
SRAM1_A7: U1.AF19(IO_L37P_2)
SRAM1_A8: U1.AF20(IO_L39P_2)
SRAM1_A9: U1.U19(IO_L12P_1)
SRAM1_A10: U1.AF23(IO_L48P_2)
SRAM1_A11: U1.AD20(IO_L41P_2)
SRAM1_A12: U1.AC19(IO_L40N_2)
SRAM1_A13: U1.W17(IO_L46P_2)
SRAM1_A14: U1.AE18(IO_L36N_2/D1)
SRAM1_A15: U1.AA17(IO_L43P_2)
SRAM1_A16: U1.AB16(IO_L38N_2)
SRAM1_A17: U1.AC16(IO_L38P_2)
SRAM1_A18: U1.W15(IO_L31N_2)
SRAM1_D0: U1.AC14(IO_L29N_2)
SRAM1_D1: U1.AE17(IO_L33P_2)
SRAM1_D2: U1.AD17(IO_L33N_2)
SRAM1_D3: U1.V17(IO_L46N_2)
SRAM1_D4: U1.V18(IO_L08P_1)
SRAM1_D5: U1.AC20(IO_L41N_2)
SRAM1_D6: U1.AC21(IO_L45N_2)
SRAM1_D7: U1.AD22(IO_L45P_2)
SRAM1_D8: U1.AD15(IO_L32P_2/AWAKE)
SRAM1_D9: U1.V14(IO_L31P_2)
SRAM1_D10: U1.AE15(IO_L32N_2/DOUT)
SRAM1_D11: U1.AE26(IO_L02P_1/LDC1)
SRAM1_D12: U1.AA22(IO_L09P_1)
SRAM1_D13: U1.AE20(IO_L39N_2)
SRAM1_D14: U1.AE19(IO_L37N_2)
SRAM1_D15: U1.V13(IO_L20P_2)
SRAM1_NBHE: U1.AC15(IO_L30P_2) ; port SRAM1.NBHE
SRAM1_NBLE: U1.AA14(IO_L27N_2/GCLK1) ; port SRAM1.NBLE
SRAM1_NCS: U1.AD14(IO_L29P_2) ; port SRAM1.NCS
SRAM1_NOE: U1.Y15(IO_L34N_2/D3) ; port SRAM1.NOE
SRAM1_NWE: U1.V16(IO_L42P_2) ; port SRAM1.NWE
SRAM2_A0: U1.U21(IO_L14P_1)
SRAM2_A1: U1.T18(IO_L17P_1)
SRAM2_A2: U1.R21(IO_L25P_1/A2)
SRAM2_A3: U1.R22(IO_L25N_1/A3)
SRAM2_A4: U1.AC25(IO_L05N_1)
SRAM2_A5: U1.T23(IO_L26P_1/A4)
SRAM2_A6: U1.R20(IO_L22N_1)
SRAM2_A7: U1.R25(IO_L29P_1/A8)
SRAM2_A8: U1.P18(IO_L34P_1/IRDY1/RHCLK6)
SRAM2_A9: U1.P22(IO_L37P_1)
SRAM2_A10: U1.P25(IO_L31N_1/TRDY1/RHCLK3)
SRAM2_A11: U1.P21(IO_L30P_1/RHCLK0)
SRAM2_A12: U1.R19(IO_L22P_1)
SRAM2_A13: U1.R26(IO_L29N_1/A9)
SRAM2_A14: U1.T24(IO_L26N_1/A5)
SRAM2_A15: U1.AD25(IO_L02N_1/LDC0)
SRAM2_A16: U1.AD26(IO_L05P_1)
SRAM2_A17: U1.Y23(IO_L13N_1)
SRAM2_A18: U1.T20(IO_L14N_1)
SRAM2_D0: U1.AA23(IO_L09N_1)
SRAM2_D1: U1.AA25(IO_L11N_1)
SRAM2_D2: U1.Y24(IO_L15P_1)
SRAM2_D3: U1.Y25(IO_L15N_1)
SRAM2_D4: U1.V22(IO_L18N_1)
SRAM2_D5: U1.V24(IO_L19P_1)
SRAM2_D6: U1.V25(IO_L19N_1)
SRAM2_D7: U1.U22(IO_L21N_1)
SRAM2_D8: U1.U20(IO_L10N_1)
SRAM2_D9: U1.U24(IO_L23N_1/VREF_1)
SRAM2_D10: U1.U23(IO_L23P_1)
SRAM2_D11: U1.V23(IO_L21P_1)
SRAM2_D12: U1.V21(IO_L10P_1)
SRAM2_D13: U1.W23(IO_L18P_1)
SRAM2_D14: U1.W21(IO_L04N_1)
SRAM2_D15: U1.Y22(IO_L13P_1)
SRAM2_NBHE: U1.AB26(IO_L06N_1) ; port SRAM2.NBHE
SRAM2_NBLE: U1.AA24(IO_L11P_1) ; port SRAM2.NBLE
SRAM2_NCS: U1.AB24(IO_L07N_1/VREF_1) ; port SRAM2.NCS
SRAM2_NOE: U1.AC26(IO_L06P_1) ; port SRAM2.NOE
SRAM2_NWE: U1.T17(IO_L17N_1) ; port SRAM2.NWE
STATUS_LED: NT6.1(Net1) ; port STATUS_LED
SUSPEND: R25.2 ; sheet U_FPGA_Power/SUSPEND
SW0: U1.AA9(IP_2/VREF_2)
SW1: U1.AF17(IP_2/VREF_2)
SW2: U1.AD9(IP_2)
SW3: U1.AD10(IP_2)
SW4: U1.AF22(IP_2/VREF_2)
TCK: R9.2 ; sheet U_FPGA_Power/TCK
TDI: R12.2 ; sheet U_FPGA_Power/TDI
TDO: R10.2 ; sheet U_FPGA_Power/TDO
TMS: R8.2 ; sheet U_FPGA_Power/TMS
NetR25_1: R25.1 U3.4(Y)

Not connected (* = marked no-connect by the designer): U1 A5(IP_0)* A7(IP_0)* A13(IP_0)* A17(IP_0)* A23(IP_0)* A24(IP_0)* AA4(IP_L58P_3)* AA8(IP_2)* AA19(IP_2)* AA20(IP_2/VREF_2)* AB3(IP_L62P_3)* AB4(IP_L62N_3)* AB10(IP_2/VREF_2)* AB17(IP_2)* AB20(IP_2)* AC5(IP_2)* AC7(IP_2)* AC17(IP_2)* AC18(IP_2)* AD5(IP_2)* AD16(IP_2)* AD23(IP_2)* AF2(IP_2)* AF7(IP_2)* B24(IP_0)* B25(IP_L65N_1)* B26(IP_L65P_1/VREF_1)* C1(IP_L04N_3/VREF_3)* C2(IP_L04P_3)* C4(IP_0)* D1(IP_L08N_3)* D2(IP_L08P_3)* D5(IP_0)* D7(IP_0/VREF_0)* D12(IP_0)* D14(IP_0/VREF_0)* D15(IP_0)* D19(IP_0)* E6(IP_0)* E9(IP_0)* E11(IP_0)* E18(IP_0)* E20(IP_0)* F9(IP_0)* F10(IP_0)* F18(IP_0)* G1(IP_L16N_3)* G2(IP_L16P_3)* G5(IP_L12P_3)* G11(IP_0/VREF_0)* G14(IP_0)* G16(IP_0)* G18(IP_0)* G25(IP_L52N_1/VREF_1)* G26(IP_L52P_1)* H4(IP_L12N_3/VREF_3)* H13(IP_0)* H18(IP_0)* H23(IP_L48P_1)* H24(IP_L48N_1)* H25(IP_L44N_1)* H26(IP_L44P_1/VREF_1)* J1(IP_L24P_3)* J2(IP_L20N_3/VREF_3)* J3(IP_L20P_3)* J10(IP_0)* J13(IP_0)* J15(IP_0)* J17(IP_0/VREF_0)* K1(IP_L24N_3)* K24(IP_L40P_1)* L10(IO_L15P_3)* L23(IP_L40N_1)* M10(IO_L21P_3)* M24(IP_L36P_1/VREF_1)* N23(IP_L36N_1)* N25(IP_L32N_1)* N26(IP_L32P_1)* P10(IO_L35N_3/LHCLK7)* R17(IO_L27N_1/A7)* R23(IP_L28P_1/VREF_1)* R24(IP_L28N_1)* U3(IP_L46P_3)* U25(IP_L24P_1)* U26(IP_L24N_1/VREF_1)* V4(IP_L46N_3)* V26(IP_L20N_1/VREF_1)* W1(IP_L50P_3)* W2(IP_L50N_3/VREF_3)* W18(IP_2)* W25(IP_L16P_1)* W26(IP_L20P_1)* Y3(IP_L54P_3)* Y4(IP_L54N_3)* Y8(IP_2)* Y11(IP_2)* Y16(IP_2/VREF_2)* Y18(IP_2)* Y19(IP_2/VREF_2)* Y26(IP_L16N_1)*; U3 1(NC)*

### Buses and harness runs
bus BUS_A[24..1]
bus BUS_D[31..0]
bus BUS_NBE[3..0]
bus DAU_TFT_BLUE[4..0]
bus DAU_TFT_CL[3..1]
bus DAU_TFT_GREEN[5..0]
bus DAU_TFT_RED[4..0]
bus DIP[7..0]
bus EXTEND_A[49..0]
bus EXTEND_B[49..0]
bus EXTEND_C[49..0]
bus FPGA_ID[3..0]
bus FPGA_M[2..0]
bus IO[35..0]
bus LED[7..0]
bus SRAM1_A[18..0]
bus SRAM1_D[15..0]
bus SRAM2_A[18..0]
bus SRAM2_D[15..0]
bus SW[4..0]

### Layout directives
net class CLKS: BUS_SDRAM_CLK, IO18, IO19, NEXUS_TCK

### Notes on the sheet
- Only Input Only Pins Here
  Do not swap into other Banks!!
- DAUGHTER BOARD I/O
- JTAG
- PROGRAM
- (near NT2) FPGA_ID = 0x0
- (near NT2) (Xilinx)
- SPI BUS
- CLOCKS
- HOST PERIPHERALS
- UPDATED
- DAUGHTER BOARD MEMORY RESOURCES
- ONE-WIRE CONNECTIONS
- TFT LCD DISPLAY INTERFACE

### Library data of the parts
NT2-NT6 NT8 = D-002-0002: as NT7 on sheet PSU
R1-R4 = D-100-0088: Resistor, 4K7 1% 0402 (1005); Power Rating: 63 mW; Resistance: 4.7 K
R8-R10 R12 R14 R18 R20 R22-R24 = D-100-0131: Resistor, 100R 1% 0402 (1005); Power Rating: 63 mW
R25 = D-100-0111: Resistor, 270R 1% 0402 (1005); Power Rating: 63 mW
U1 = D-241-0013: FPGA, Xilinx Spartan 3A-DSP-1800 FG676; Supply Voltage: mV
U3 = D-205-0001: SN74LVC1G04DBV, Single Inverter Gate, 1.65-V to 5.5-V

## Sheet FPGA_NonIO.SchDoc: FPGA Power and Programming
size A4; Organization: Altium Limited.; Address1: Level 3, 12a Rodborough Rd; Address2: Frenchs Forest 2086; Address3: NSW; Address4: AUSTRALIA; DocumentNumber: 8; SheetNumber: 8; SheetTotal: 23
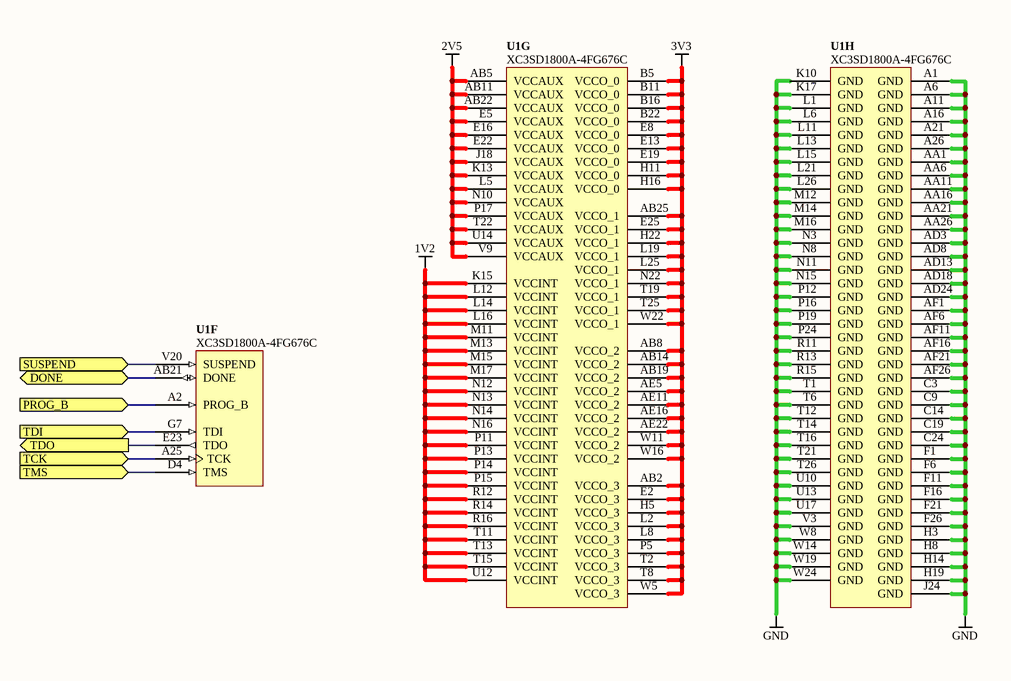
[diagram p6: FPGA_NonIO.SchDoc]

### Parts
U1  XC3SD1800A-4FG676C  [BGA100P26X26-676]  (parts F,G,H of 8)

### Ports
DONE (bidir), PROG_B (in), SUSPEND (in), TCK (in), TDI (in), TDO (out), TMS (in)

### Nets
1V2: U1.K15(VCCINT) U1.L12(VCCINT) U1.L14(VCCINT) U1.L16(VCCINT) U1.M11(VCCINT) U1.M13(VCCINT) U1.M15(VCCINT) U1.M17(VCCINT) U1.N12(VCCINT) U1.N13(VCCINT) U1.N14(VCCINT) U1.N16(VCCINT) U1.P11(VCCINT) U1.P13(VCCINT) U1.P14(VCCINT) U1.P15(VCCINT) U1.R12(VCCINT) U1.R14(VCCINT) U1.R16(VCCINT) U1.T11(VCCINT) U1.T13(VCCINT) U1.T15(VCCINT) U1.U12(VCCINT)
2V5: U1.AB5(VCCAUX) U1.AB11(VCCAUX) U1.AB22(VCCAUX) U1.E5(VCCAUX) U1.E16(VCCAUX) U1.E22(VCCAUX) U1.J18(VCCAUX) U1.K13(VCCAUX) U1.L5(VCCAUX) U1.N10(VCCAUX) U1.P17(VCCAUX) U1.T22(VCCAUX) U1.U14(VCCAUX) U1.V9(VCCAUX)
3V3: U1.AB2(VCCO_3) U1.AB8(VCCO_2) U1.AB14(VCCO_2) U1.AB19(VCCO_2) U1.AB25(VCCO_1) U1.AE5(VCCO_2) U1.AE11(VCCO_2) U1.AE16(VCCO_2) U1.AE22(VCCO_2) U1.B5(VCCO_0) U1.B11(VCCO_0) U1.B16(VCCO_0) U1.B22(VCCO_0) U1.E2(VCCO_3) U1.E8(VCCO_0) U1.E13(VCCO_0) U1.E19(VCCO_0) U1.E25(VCCO_1) U1.H5(VCCO_3) U1.H11(VCCO_0) U1.H16(VCCO_0) U1.H22(VCCO_1) U1.L2(VCCO_3) U1.L8(VCCO_3) U1.L19(VCCO_1) U1.L25(VCCO_1) U1.N22(VCCO_1) U1.P5(VCCO_3) U1.T2(VCCO_3) U1.T8(VCCO_3) U1.T19(VCCO_1) U1.T25(VCCO_1) U1.W5(VCCO_3) U1.W11(VCCO_2) U1.W16(VCCO_2) U1.W22(VCCO_1)
GND: U1.A1(GND) U1.A6(GND) U1.A11(GND) U1.A16(GND) U1.A21(GND) U1.A26(GND) U1.AA1(GND) U1.AA6(GND) U1.AA11(GND) U1.AA16(GND) U1.AA21(GND) U1.AA26(GND) U1.AD3(GND) U1.AD8(GND) U1.AD13(GND) U1.AD18(GND) U1.AD24(GND) U1.AF1(GND) U1.AF6(GND) U1.AF11(GND) U1.AF16(GND) U1.AF21(GND) U1.AF26(GND) U1.C3(GND) U1.C9(GND) U1.C14(GND) U1.C19(GND) U1.C24(GND) U1.F1(GND) U1.F6(GND) U1.F11(GND) U1.F16(GND) U1.F21(GND) U1.F26(GND) U1.H3(GND) U1.H8(GND) U1.H14(GND) U1.H19(GND) U1.J24(GND) U1.K10(GND) U1.K17(GND) U1.L1(GND) U1.L6(GND) U1.L11(GND) U1.L13(GND) U1.L15(GND) U1.L21(GND) U1.L26(GND) U1.M12(GND) U1.M14(GND) U1.M16(GND) U1.N3(GND) U1.N8(GND) U1.N11(GND) U1.N15(GND) U1.P12(GND) U1.P16(GND) U1.P19(GND) U1.P24(GND) U1.R11(GND) U1.R13(GND) U1.R15(GND) U1.T1(GND) U1.T6(GND) U1.T12(GND) U1.T14(GND) U1.T16(GND) U1.T21(GND) U1.T26(GND) U1.U10(GND) U1.U13(GND) U1.U17(GND) U1.V3(GND) U1.W8(GND) U1.W14(GND) U1.W19(GND) U1.W24(GND)
DONE: U1.AB21(DONE) ; port DONE
PROG_B: U1.A2(PROG_B) ; port PROG_B
SUSPEND: U1.V20(SUSPEND) ; port SUSPEND
TCK: U1.A25(TCK) ; port TCK
TDI: U1.G7(TDI) ; port TDI
TDO: U1.E23(TDO) ; port TDO
TMS: U1.D4(TMS) ; port TMS

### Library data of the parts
U1 = D-241-0013: as U1 on sheet FPGA

## Sheet Bypass_FPGA_3V3.SchDoc: FPGA Bypass 3V3
size A4; Organization: Altium Limited.; Address1: Level 3, 12a Rodborough Rd; Address2: Frenchs Forest 2086; Address3: NSW; Address4: AUSTRALIA; DocumentNumber: 7; SheetNumber: 7; SheetTotal: 23; PageSetup: Record=PageOptions|CenterHorizontal=True|CenterVertical=True|PrintScale=0.97|XCorrection=1.00|YCorrection=1.00|PrintKind=0|BorderSize=5000000|LeftOffset=0|BottomOffset=0|Orientation=2|PaperLength=1000|PaperWidth=1000|Scale=100|PaperSource=7|PrintQuality=-4|MediaType=1|DitherType=10|PaperKind=A4 (210 x 297 mm)|PrintScaleMode=1
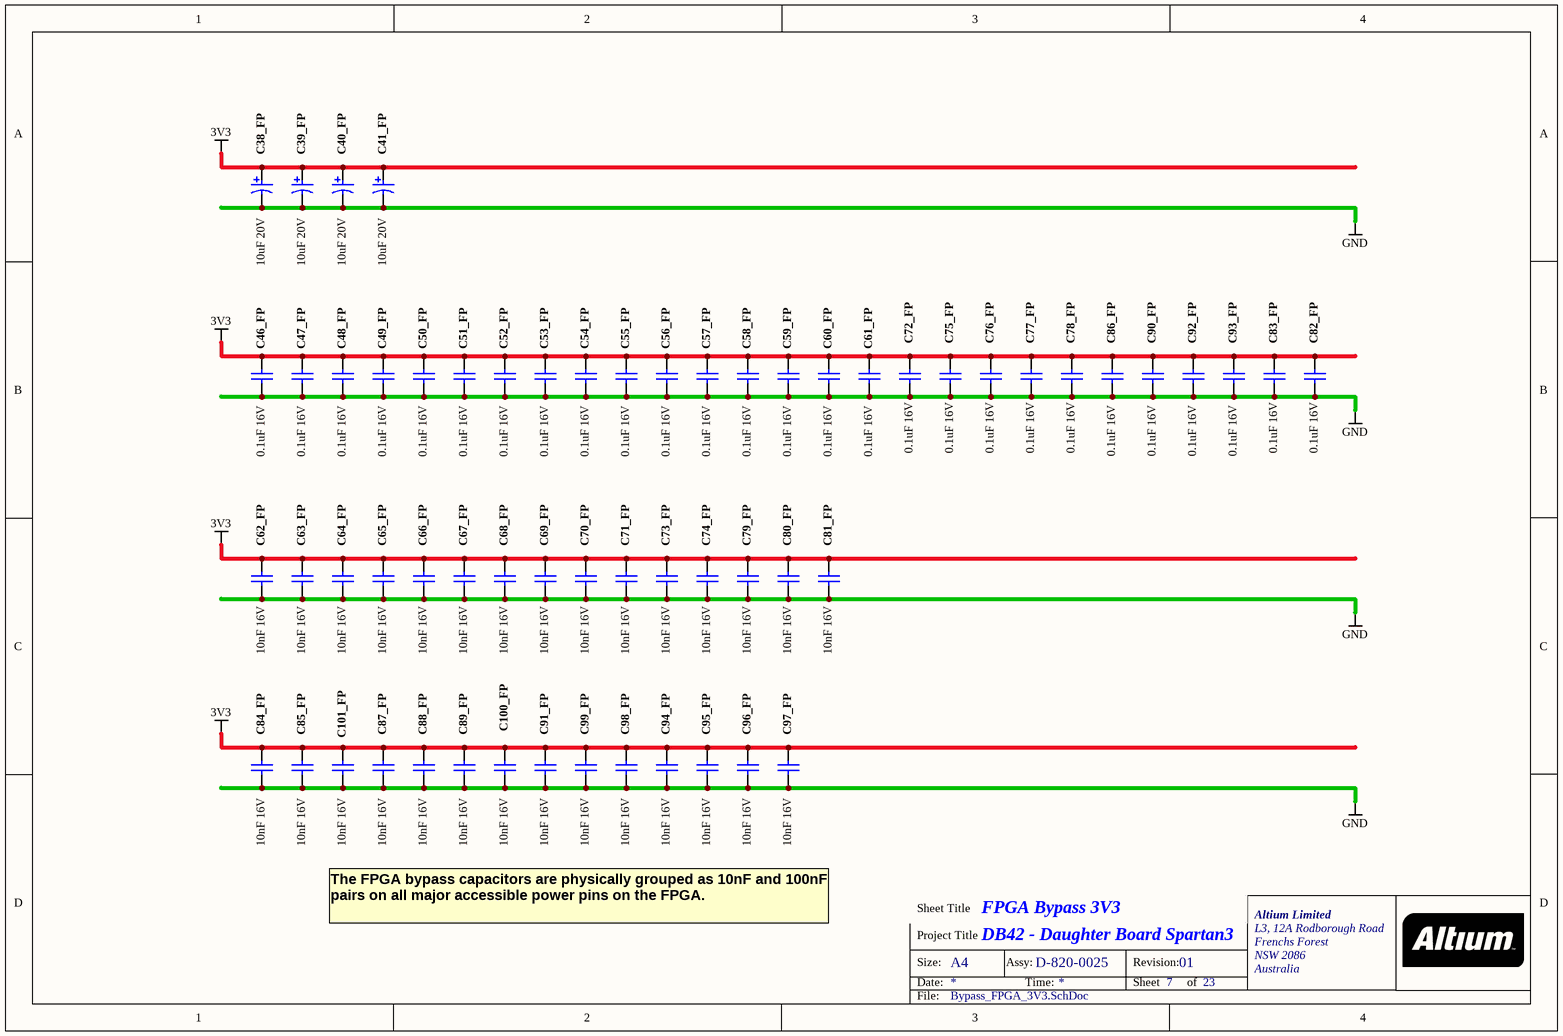
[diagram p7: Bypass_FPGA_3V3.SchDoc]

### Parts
C38_FP  10uF 20V  [CAPC3528-STAR]
C39_FP  10uF 20V  [CAPC3528-STAR]
C40_FP  10uF 20V  [CAPC3528-STAR]
C41_FP  10uF 20V  [CAPC3528-STAR]
C46_FP  0.1uF 16V  [CAPC1005-STAR]
C47_FP  0.1uF 16V  [CAPC1005-STAR]
C48_FP  0.1uF 16V  [CAPC1005-STAR]
C49_FP  0.1uF 16V  [CAPC1005-STAR]
C50_FP  0.1uF 16V  [CAPC1005-STAR]
C51_FP  0.1uF 16V  [CAPC1005-STAR]
C52_FP  0.1uF 16V  [CAPC1005-STAR]
C53_FP  0.1uF 16V  [CAPC1005-STAR]
C54_FP  0.1uF 16V  [CAPC1005-STAR]
C55_FP  0.1uF 16V  [CAPC1005-STAR]
C56_FP  0.1uF 16V  [CAPC1005-STAR]
C57_FP  0.1uF 16V  [CAPC1005-STAR]
C58_FP  0.1uF 16V  [CAPC1005-STAR]
C59_FP  0.1uF 16V  [CAPC1005-STAR]
C60_FP  0.1uF 16V  [CAPC1005-STAR]
C61_FP  0.1uF 16V  [CAPC1005-STAR]
C62_FP  10nF 16V  [CAPC1005-STAR]
C63_FP  10nF 16V  [CAPC1005-STAR]
C64_FP  10nF 16V  [CAPC1005-STAR]
C65_FP  10nF 16V  [CAPC1005-STAR]
C66_FP  10nF 16V  [CAPC1005-STAR]
C67_FP  10nF 16V  [CAPC1005-STAR]
C68_FP  10nF 16V  [CAPC1005-STAR]
C69_FP  10nF 16V  [CAPC1005-STAR]
C70_FP  10nF 16V  [CAPC1005-STAR]
C71_FP  10nF 16V  [CAPC1005-STAR]
C72_FP  0.1uF 16V  [CAPC1005-STAR]
C73_FP  10nF 16V  [CAPC1005-STAR]
C74_FP  10nF 16V  [CAPC1005-STAR]
C75_FP  0.1uF 16V  [CAPC1005-STAR]
C76_FP  0.1uF 16V  [CAPC1005-STAR]
C77_FP  0.1uF 16V  [CAPC1005-STAR]
C78_FP  0.1uF 16V  [CAPC1005-STAR]
C79_FP  10nF 16V  [CAPC1005-STAR]
C80_FP  10nF 16V  [CAPC1005-STAR]
C81_FP  10nF 16V  [CAPC1005-STAR]
C82_FP  0.1uF 16V  [CAPC1005-STAR]
C83_FP  0.1uF 16V  [CAPC1005-STAR]
C84_FP  10nF 16V  [CAPC1005-STAR]
C85_FP  10nF 16V  [CAPC1005-STAR]
C86_FP  0.1uF 16V  [CAPC1005-STAR]
C87_FP  10nF 16V  [CAPC1005-STAR]
C88_FP  10nF 16V  [CAPC1005-STAR]
C89_FP  10nF 16V  [CAPC1005-STAR]
C90_FP  0.1uF 16V  [CAPC1005-STAR]
C91_FP  10nF 16V  [CAPC1005-STAR]
C92_FP  0.1uF 16V  [CAPC1005-STAR]
C93_FP  0.1uF 16V  [CAPC1005-STAR]
C94_FP  10nF 16V  [CAPC1005-STAR]
C95_FP  10nF 16V  [CAPC1005-STAR]
C96_FP  10nF 16V  [CAPC1005-STAR]
C97_FP  10nF 16V  [CAPC1005-STAR]
C98_FP  10nF 16V  [CAPC1005-STAR]
C99_FP  10nF 16V  [CAPC1005-STAR]
C100_FP  10nF 16V  [CAPC1005-STAR]
C101_FP  10nF 16V  [CAPC1005-STAR]

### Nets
3V3: C38_FP.1 C39_FP.1 C40_FP.1 C41_FP.1 C46_FP.1 C47_FP.1 C48_FP.1 C49_FP.1 C50_FP.1 C51_FP.1 C52_FP.1 C53_FP.1 C54_FP.1 C55_FP.1 C56_FP.1 C57_FP.1 C58_FP.1 C59_FP.1 C60_FP.1 C61_FP.1 C62_FP.1 C63_FP.1 C64_FP.1 C65_FP.1 C66_FP.1 C67_FP.1 C68_FP.1 C69_FP.1 C70_FP.1 C71_FP.1 C72_FP.1 C73_FP.1 C74_FP.1 C75_FP.1 C76_FP.1 C77_FP.1 C78_FP.1 C79_FP.1 C80_FP.1 C81_FP.1 C82_FP.1 C83_FP.1 C84_FP.1 C85_FP.1 C86_FP.1 C87_FP.1 C88_FP.1 C89_FP.1 C90_FP.1 C91_FP.1 C92_FP.1 C93_FP.1 C94_FP.1 C95_FP.1 C96_FP.1 C97_FP.1 C98_FP.1 C99_FP.1 C100_FP.1 C101_FP.1
GND: C38_FP.2 C39_FP.2 C40_FP.2 C41_FP.2 C46_FP.2 C47_FP.2 C48_FP.2 C49_FP.2 C50_FP.2 C51_FP.2 C52_FP.2 C53_FP.2 C54_FP.2 C55_FP.2 C56_FP.2 C57_FP.2 C58_FP.2 C59_FP.2 C60_FP.2 C61_FP.2 C62_FP.2 C63_FP.2 C64_FP.2 C65_FP.2 C66_FP.2 C67_FP.2 C68_FP.2 C69_FP.2 C70_FP.2 C71_FP.2 C72_FP.2 C73_FP.2 C74_FP.2 C75_FP.2 C76_FP.2 C77_FP.2 C78_FP.2 C79_FP.2 C80_FP.2 C81_FP.2 C82_FP.2 C83_FP.2 C84_FP.2 C85_FP.2 C86_FP.2 C87_FP.2 C88_FP.2 C89_FP.2 C90_FP.2 C91_FP.2 C92_FP.2 C93_FP.2 C94_FP.2 C95_FP.2 C96_FP.2 C97_FP.2 C98_FP.2 C99_FP.2 C100_FP.2 C101_FP.2

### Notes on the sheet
- The FPGA bypass capacitors are physically grouped as 10nF and 100nF pairs on all major accessible power pins on the FPGA.

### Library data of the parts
C38_FP C39_FP C40_FP C41_FP = D-101-0007: Capacitor, Tantalum, 10uF 10% 20V MCCT-B (3528); Polarity: Polarized
C46_FP C47_FP C48_FP C49_FP C50_FP C51_FP C52_FP C53_FP C54_FP C55_FP C56_FP C57_FP C58_FP C59_FP C60_FP C61_FP C72_FP C75_FP C76_FP C77_FP C78_FP C82_FP C83_FP C86_FP C90_FP C92_FP C93_FP = D-101-0080: Capacitor, Ceramic, 0.1uF 10% 16V 0402 (1005) X7R; Polarity: Non-Polarized
C62_FP C63_FP C64_FP C65_FP C66_FP C67_FP C68_FP C69_FP C70_FP C71_FP C73_FP C74_FP C79_FP C80_FP C81_FP C84_FP C85_FP C87_FP C88_FP C89_FP C91_FP C94_FP C95_FP C96_FP C97_FP C98_FP C99_FP C100_FP C101_FP = D-101-0077: Capacitor, Ceramic, 10nF 10% 16V 0402 (1005) X7R; Polarity: Non-Polarized

## Sheet Bypass_FPGA_2V5.SchDoc: FPGA Bypass 2V5
size A4; Organization: Altium Limited.; Address1: Level 3, 12a Rodborough Rd; Address2: Frenchs Forest 2086; Address3: NSW; Address4: AUSTRALIA; DocumentNumber: 6; SheetNumber: 6; SheetTotal: 23; PageSetup: Record=PageOptions|CenterHorizontal=True|CenterVertical=True|PrintScale=0.97|XCorrection=1.00|YCorrection=1.00|PrintKind=0|BorderSize=5000000|LeftOffset=0|BottomOffset=0|Orientation=2|PaperLength=1000|PaperWidth=1000|Scale=100|PaperSource=7|PrintQuality=-4|MediaType=1|DitherType=10|PaperKind=A4 (210 x 297 mm)|PrintScaleMode=1
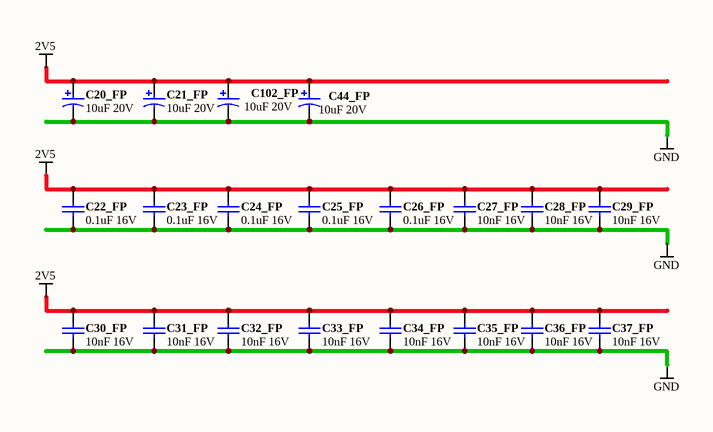
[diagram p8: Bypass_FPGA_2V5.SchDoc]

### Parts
C20_FP  10uF 20V  [CAPC3528-STAR]
C21_FP  10uF 20V  [CAPC3528-STAR]
C22_FP  0.1uF 16V  [CAPC1005-STAR]
C23_FP  0.1uF 16V  [CAPC1005-STAR]
C24_FP  0.1uF 16V  [CAPC1005-STAR]
C25_FP  0.1uF 16V  [CAPC1005-STAR]
C26_FP  0.1uF 16V  [CAPC1005-STAR]
C27_FP  10nF 16V  [CAPC1005-STAR]
C28_FP  10nF 16V  [CAPC1005-STAR]
C29_FP  10nF 16V  [CAPC1005-STAR]
C30_FP  10nF 16V  [CAPC1005-STAR]
C31_FP  10nF 16V  [CAPC1005-STAR]
C32_FP  10nF 16V  [CAPC1005-STAR]
C33_FP  10nF 16V  [CAPC1005-STAR]
C34_FP  10nF 16V  [CAPC1005-STAR]
C35_FP  10nF 16V  [CAPC1005-STAR]
C36_FP  10nF 16V  [CAPC1005-STAR]
C37_FP  10nF 16V  [CAPC1005-STAR]
C44_FP  10uF 20V  [CAPC3528-STAR]
C102_FP  10uF 20V  [CAPC3528-STAR]

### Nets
2V5: C20_FP.1 C21_FP.1 C22_FP.1 C23_FP.1 C24_FP.1 C25_FP.1 C26_FP.1 C27_FP.1 C28_FP.1 C29_FP.1 C30_FP.1 C31_FP.1 C32_FP.1 C33_FP.1 C34_FP.1 C35_FP.1 C36_FP.1 C37_FP.1 C44_FP.1 C102_FP.1
GND: C20_FP.2 C21_FP.2 C22_FP.2 C23_FP.2 C24_FP.2 C25_FP.2 C26_FP.2 C27_FP.2 C28_FP.2 C29_FP.2 C30_FP.2 C31_FP.2 C32_FP.2 C33_FP.2 C34_FP.2 C35_FP.2 C36_FP.2 C37_FP.2 C44_FP.2 C102_FP.2

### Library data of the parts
C20_FP C21_FP C44_FP C102_FP = D-101-0007: as C38_FP on sheet Bypass_FPGA_3V3
C22_FP C23_FP C24_FP C25_FP C26_FP = D-101-0080: as C46_FP on sheet Bypass_FPGA_3V3
C27_FP C28_FP C29_FP C30_FP C31_FP C32_FP C33_FP C34_FP C35_FP C36_FP C37_FP = D-101-0077: as C62_FP on sheet Bypass_FPGA_3V3

## Sheet Bypass_FPGA_1V2.SchDoc: FPGA Bypass 1V2
size A4; Organization: Altium Limited.; Address1: Level 3, 12a Rodborough Rd; Address2: Frenchs Forest 2086; Address3: NSW; Address4: AUSTRALIA; DocumentNumber: 5; SheetNumber: 5; SheetTotal: 23; PageSetup: Record=PageOptions|CenterHorizontal=True|CenterVertical=True|PrintScale=0.97|XCorrection=1.00|YCorrection=1.00|PrintKind=0|BorderSize=5000000|LeftOffset=0|BottomOffset=0|Orientation=2|PaperLength=1000|PaperWidth=1000|Scale=100|PaperSource=7|PrintQuality=-4|MediaType=1|DitherType=10|PaperKind=A4 (210 x 297 mm)|PrintScaleMode=1
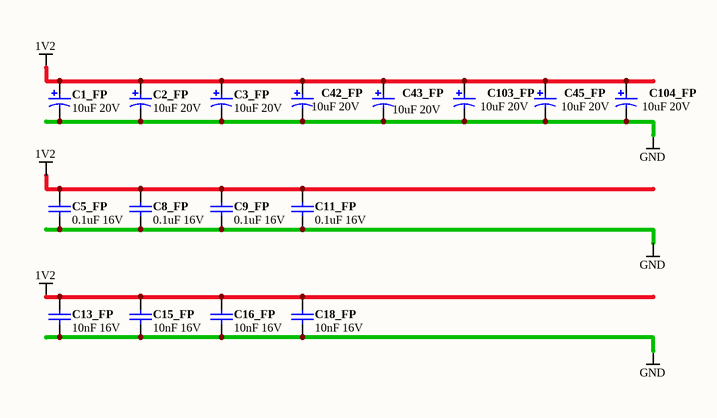
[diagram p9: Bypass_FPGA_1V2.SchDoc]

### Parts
C1_FP  10uF 20V  [CAPC3528-STAR]
C2_FP  10uF 20V  [CAPC3528-STAR]
C3_FP  10uF 20V  [CAPC3528-STAR]
C5_FP  0.1uF 16V  [CAPC1005-STAR]
C8_FP  0.1uF 16V  [CAPC1005-STAR]
C9_FP  0.1uF 16V  [CAPC1005-STAR]
C11_FP  0.1uF 16V  [CAPC1005-STAR]
C13_FP  10nF 16V  [CAPC1005-STAR]
C15_FP  10nF 16V  [CAPC1005-STAR]
C16_FP  10nF 16V  [CAPC1005-STAR]
C18_FP  10nF 16V  [CAPC1005-STAR]
C42_FP  10uF 20V  [CAPC3528-STAR]
C43_FP  10uF 20V  [CAPC3528-STAR]
C45_FP  10uF 20V  [CAPC3528-STAR]
C103_FP  10uF 20V  [CAPC3528-STAR]
C104_FP  10uF 20V  [CAPC3528-STAR]

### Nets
1V2: C1_FP.1 C2_FP.1 C3_FP.1 C5_FP.1 C8_FP.1 C9_FP.1 C11_FP.1 C13_FP.1 C15_FP.1 C16_FP.1 C18_FP.1 C42_FP.1 C43_FP.1 C45_FP.1 C103_FP.1 C104_FP.1
GND: C1_FP.2 C2_FP.2 C3_FP.2 C5_FP.2 C8_FP.2 C9_FP.2 C11_FP.2 C13_FP.2 C15_FP.2 C16_FP.2 C18_FP.2 C42_FP.2 C43_FP.2 C45_FP.2 C103_FP.2 C104_FP.2

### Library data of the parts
C1_FP C2_FP C3_FP C42_FP C43_FP C45_FP C103_FP C104_FP = D-101-0007: as C38_FP on sheet Bypass_FPGA_3V3
C5_FP C8_FP C9_FP C11_FP = D-101-0080: as C46_FP on sheet Bypass_FPGA_3V3
C13_FP C15_FP C16_FP C18_FP = D-101-0077: as C62_FP on sheet Bypass_FPGA_3V3

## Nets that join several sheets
1V2: PSU (TP4.1), FPGA_NonIO (23 pins), Bypass_FPGA_1V2 (16 pins)
2V5: PSU (R1T.2 TP2.1), FPGA_NonIO (14 pins), Bypass_FPGA_2V5 (20 pins)
3V3: PSU (C23_CM.1 C24_CM.1 TP1.1), FPGA (5 pins), FPGA_NonIO (36 pins), Bypass_FPGA_3V3 (60 pins)
GND: PSU (C23_CM.2 C24_CM.2 NT7.2 TP0.1), FPGA (5 pins), FPGA_NonIO (77 pins), Bypass_FPGA_3V3 (60 pins), Bypass_FPGA_2V5 (20 pins), Bypass_FPGA_1V2 (16 pins)
DONE: FPGA (R22.2), FPGA_NonIO (U1.AB21)
PROG_B: FPGA (R24.2), FPGA_NonIO (U1.A2)
SUSPEND: FPGA (R25.2), FPGA_NonIO (U1.V20)
TCK: FPGA (R9.2), FPGA_NonIO (U1.A25)
TDI: FPGA (R12.2), FPGA_NonIO (U1.G7)
TDO: FPGA (R10.2), FPGA_NonIO (U1.E23)
TMS: FPGA (R8.2), FPGA_NonIO (U1.D4)

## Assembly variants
Production: not fitted RN1 RN2 RN3 RN4 RN5 RN6 RN7 RN8 RN17 RN18 RN19 RN20 RN21 RN22 RN23 RN24 RN25 RN26 RN27 RN28 RN29 RN30 RN31 RN32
